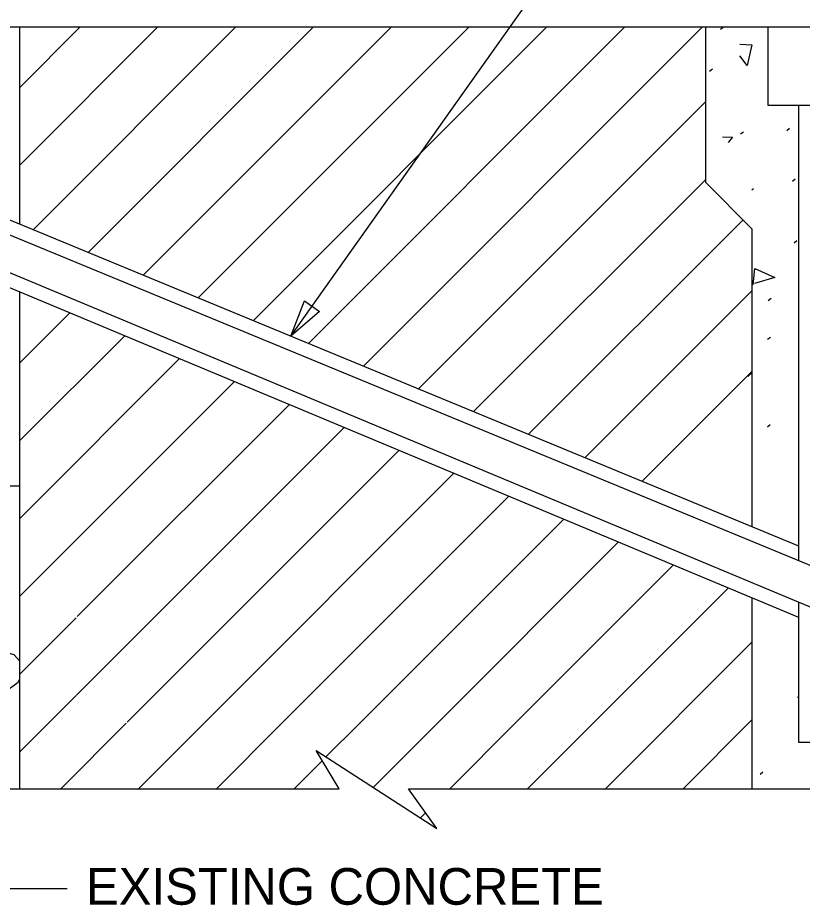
# Model space of a CAD drawing. Extents: x 3239 to 4230, y -4276 to -2494.
# Drawn here: x 3615.4 to 3679.6, y -3464.3 to -3391.8 of the extents above; entities that cross this region are included whole.
import ezdxf

# ---------------------------------------------------------------- set-up
doc = ezdxf.new("R2010")
doc.units = 0
doc.layers.add('2', color=7, linetype='Continuous')

msp = doc.modelspace()

# ---------------------------------------------------------------- linework, layer by layer
at = {"layer": '2'}
for p, q in [((3432.777, -3392.515), (3671.69, -3392.515)), ((3615.577, -3392.515), (3615.577, -3408.632)), ((3615.577, -3397.48), (3620.541, -3392.515)), ((3615.643, -3403.778), (3626.905, -3392.515)), ((3616.692, -3409.093), (3633.269, -3392.515)), ((3621.196, -3410.953), (3639.633, -3392.515)), ((3625.7, -3412.812), (3645.997, -3392.515)), ((3630.204, -3414.672), (3652.361, -3392.515)), ((3634.708, -3416.532), (3658.725, -3392.515)), ((3639.212, -3418.392), (3665.089, -3392.515)), ((3643.716, -3420.252), (3671.453, -3392.515)), ((3671.69, -3392.515), (3676.79, -3392.515)), ((3671.69, -3392.515), (3671.69, -3405.215)), ((3672.933, -3392.69), (3673.166, -3392.504)), ((3676.79, -3392.515), (3676.79, -3398.915)), ((3676.79, -3392.515), (3676.79, -3393.815)), ((3676.79, -3392.515), (3732.59, -3392.515)), ((3585.357, -3396.154), (3679.29, -3434.941)), ((3672.025, -3396.115), (3672.258, -3395.929)), ((3584.929, -3397.191), (3697.703, -3443.758)), ((3648.22, -3422.112), (3671.69, -3398.643)), ((3676.79, -3398.915), (3679.29, -3398.915)), ((3679.29, -3398.915), (3730.09, -3398.915)), ((3679.29, -3398.915), (3679.29, -3436.155)), ((3583.873, -3399.72), (3695.049, -3446.137)), ((3583.44, -3400.756), (3679.29, -3440.774)), ((3678.339, -3400.984), (3678.571, -3400.798)), ((3674.564, -3401.264), (3674.797, -3401.078)), ((3652.724, -3423.972), (3671.69, -3405.006)), ((3678.802, -3405.129), (3679.035, -3404.942)), ((3671.69, -3405.215), (3675.49, -3409.015)), ((3675.49, -3405.823), (3675.624, -3405.716)), ((3657.228, -3425.831), (3674.767, -3408.293)), ((3675.49, -3409.015), (3675.49, -3433.372)), ((3678.942, -3410.161), (3679.175, -3409.975)), ((3615.577, -3414.173), (3615.577, -3423.015)), ((3661.838, -3427.735), (3675.49, -3414.083)), ((3676.822, -3414.891), (3677.054, -3414.704)), ((3615.577, -3420.01), (3619.695, -3415.892)), ((3615.577, -3426.374), (3624.184, -3417.766)), ((3676.775, -3418.059), (3677.008, -3417.873)), ((3615.577, -3432.738), (3628.674, -3419.641)), ((3666.517, -3429.667), (3675.49, -3420.694)), ((3675.171, -3421.109), (3675.49, -3420.79)), ((3615.577, -3439.102), (3633.163, -3421.515)), ((3615.577, -3423.015), (3615.577, -3454.815)), ((3620.306, -3440.736), (3637.653, -3423.39)), ((3620.242, -3447.164), (3642.142, -3425.264)), ((3676.758, -3425.209), (3676.991, -3425.022)), ((3624.396, -3449.374), (3646.632, -3427.139)), ((3630.683, -3449.451), (3651.121, -3429.013)), ((3380.058, -3430.046), (3615.577, -3430.046)), ((3636.924, -3449.574), (3655.611, -3430.887)), ((3643.304, -3449.559), (3660.1, -3432.762)), ((3649.683, -3449.543), (3664.59, -3434.636)), ((3655.97, -3449.62), (3669.079, -3436.511)), ((3657.139, -3454.815), (3673.569, -3438.385)), ((3675.49, -3439.187), (3675.49, -3454.815)), ((3679.29, -3439.558), (3679.29, -3451.015)), ((3615.577, -3445.466), (3620.205, -3440.838)), ((3663.503, -3454.815), (3675.49, -3442.829)), ((3615.577, -3451.83), (3620.205, -3447.202)), ((3679.231, -3447.341), (3679.29, -3447.294)), ((3669.867, -3454.815), (3675.49, -3449.193)), ((3618.955, -3454.815), (3624.314, -3449.456)), ((3625.319, -3454.815), (3630.678, -3449.456)), ((3631.683, -3454.815), (3637.042, -3449.456)), ((3640.645, -3452.217), (3643.406, -3449.456)), ((3644.514, -3454.712), (3649.77, -3449.456)), ((3650.775, -3454.815), (3656.134, -3449.456)), ((3679.29, -3451.015), (3730.09, -3451.015)), ((3641.728, -3454.815), (3639.835, -3451.694)), ((3639.835, -3451.694), (3649.704, -3458.06)), ((3638.047, -3454.815), (3640.338, -3452.524)), ((3676.156, -3453.631), (3676.389, -3453.445)), ((3515.43, -3454.815), (3641.728, -3454.815)), ((3647.396, -3454.815), (3675.49, -3454.815)), ((3649.704, -3458.06), (3647.396, -3454.815)), ((3675.49, -3454.815), (3733.89, -3454.815)), ((3648.382, -3457.208), (3648.8, -3456.79))]:
    msp.add_line(p, q, dxfattribs=at)
for points in [[(3637.777, -3417.8), (3667.315, -3376.157), (3677.078, -3376.157)], [(3674.505, -3393.928), (3675.488, -3393.975), (3675.092, -3395.676), (3674.505, -3394.885)], [(3673.085, -3401.51), (3673.895, -3401.52), (3673.545, -3401.97)], [(3675.587, -3413.609), (3675.727, -3412.258), (3677.357, -3413.004), (3675.703, -3413.493)], [(3583.14, -3416.497), (3614.699, -3462.967), (3619.467, -3462.967)], [(3611.717, -3444.47), (3611.237, -3444.206), (3611.058, -3443.918), (3610.261, -3443.529), (3609.644, -3443.431), (3609.086, -3443.785), (3608.532, -3444.443), (3607.867, -3445.547), (3607.959, -3446.607), (3608.231, -3447.956), (3608.406, -3448.225), (3609.696, -3449.026), (3610.761, -3449.238), (3611.946, -3448.829), (3612.668, -3448.614), (3613.109, -3448.424), (3614.091, -3447.444), (3614.76, -3446.623), (3615.477, -3446.103), (3615.577, -3445.898)], [(3615.577, -3444.366), (3615.129, -3443.866), (3613.585, -3443.392), (3612.702, -3443.774), (3611.998, -3444.445), (3611.869, -3444.456)]]:
    msp.add_lwpolyline(points, dxfattribs=at)
msp.add_lwpolyline([(3640.125, -3415.786), (3637.777, -3417.8), (3638.901, -3414.919)], close=True, dxfattribs=at)

# ---------------------------------------------------------------- texts
msp.add_text('EXISTING CONCRETE', height=3, dxfattribs=at).set_placement((3621.023, -3464.306))

doc.saveas('drawing.dxf')
